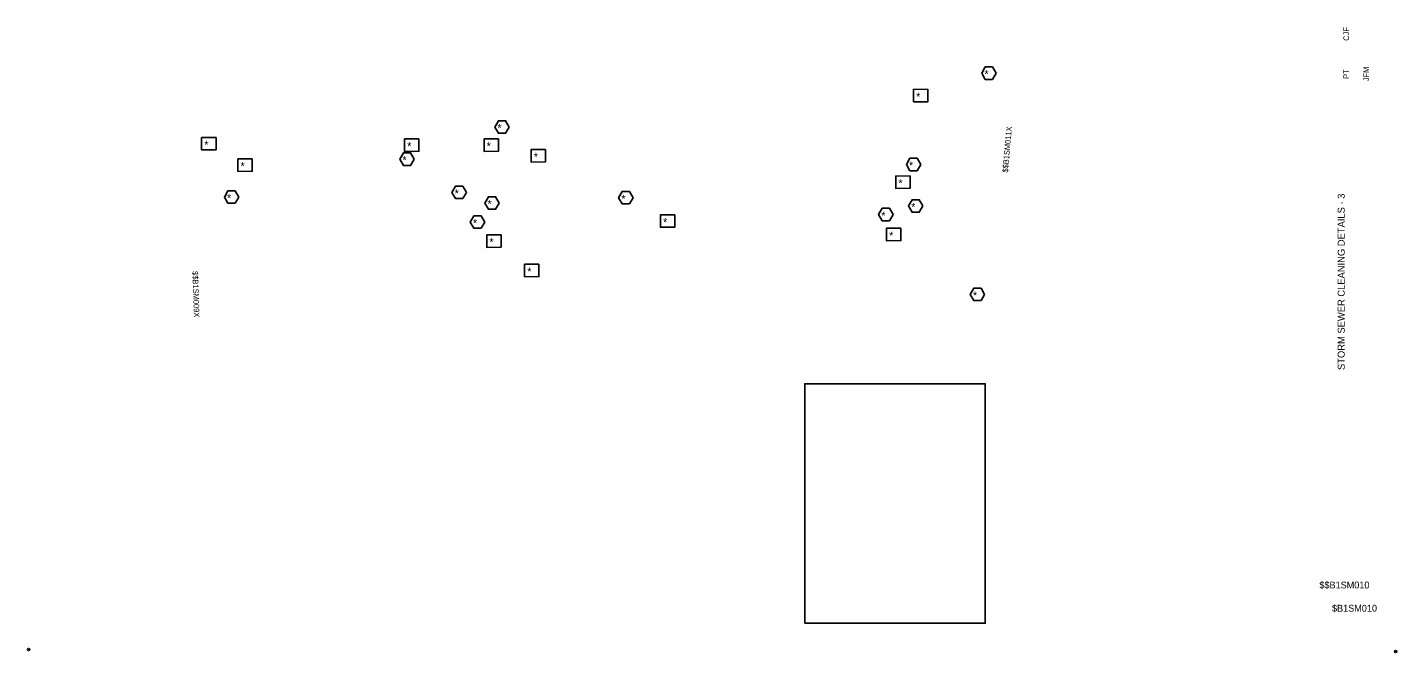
# Model space of a CAD drawing. Extents: x -0.1 to 34.1, y 0.1 to 15.7.
import ezdxf

# ---------------------------------------------------------------- set-up
doc = ezdxf.new("R2010")
doc.units = 0
for name, color, linetype in [('Default', 7, 'Continuous'), ('SC_Scratch1', 7, 'Continuous'), ('SH_Data', 7, 'Continuous')]:
    doc.layers.add(name, color=color, linetype=linetype)

msp = doc.modelspace()

# ---------------------------------------------------------------- linework, layer by layer
at = {"layer": 'Default'}
for p, q in [((-0.132, 0.139), (-0.08, 0.139)), ((-0.106, 0.139), (-0.057, 0.139)), ((34.043, 0.087), (34.095, 0.087)), ((34.069, 0.087), (34.118, 0.087))]:
    msp.add_line(p, q, dxfattribs=at)
msp.add_lwpolyline([(19.3, 0.793), (23.813, 0.793), (23.813, 6.783), (19.3, 6.783)], close=True, dxfattribs=at)
for centre in [(-0.106, 0.139), (34.069, 0.087)]:
    msp.add_circle(centre, 0.026, dxfattribs=at)
at = {"layer": 'SC_Scratch1'}
for points in [[(24.082, 14.545), (23.992, 14.701), (23.812, 14.701), (23.722, 14.545), (23.812, 14.389), (23.992, 14.389)], [(22.376, 14.143), (22.016, 14.139), (22.016, 13.828), (22.376, 13.832)], [(11.911, 13.198), (11.821, 13.354), (11.641, 13.354), (11.551, 13.198), (11.641, 13.042), (11.821, 13.042)], [(4.583, 12.94), (4.223, 12.936), (4.223, 12.625), (4.583, 12.629)], [(9.656, 12.905), (9.296, 12.901), (9.296, 12.589), (9.656, 12.593)], [(11.641, 12.905), (11.282, 12.901), (11.282, 12.589), (11.641, 12.593)], [(5.489, 12.405), (5.129, 12.402), (5.129, 12.09), (5.489, 12.094)], [(9.536, 12.395), (9.446, 12.551), (9.266, 12.551), (9.176, 12.395), (9.266, 12.24), (9.446, 12.24)], [(12.818, 12.639), (12.458, 12.635), (12.458, 12.323), (12.818, 12.327)], [(22.199, 12.263), (22.109, 12.418), (21.929, 12.418), (21.839, 12.263), (21.929, 12.107), (22.109, 12.107)], [(10.84, 11.565), (10.75, 11.72), (10.57, 11.72), (10.48, 11.565), (10.57, 11.409), (10.75, 11.409)], [(21.934, 11.978), (21.574, 11.974), (21.574, 11.662), (21.934, 11.666)], [(5.151, 11.449), (5.061, 11.605), (4.881, 11.605), (4.791, 11.449), (4.881, 11.293), (5.061, 11.293)], [(11.662, 11.299), (11.572, 11.454), (11.392, 11.454), (11.302, 11.299), (11.392, 11.143), (11.572, 11.143)], [(15.006, 11.432), (14.916, 11.588), (14.736, 11.588), (14.646, 11.432), (14.736, 11.276), (14.916, 11.276)], [(22.252, 11.226), (22.162, 11.382), (21.982, 11.382), (21.892, 11.226), (21.982, 11.07), (22.162, 11.07)], [(11.298, 10.822), (11.208, 10.978), (11.028, 10.978), (10.939, 10.822), (11.028, 10.666), (11.208, 10.666)], [(16.05, 11.006), (15.691, 11.002), (15.691, 10.691), (16.05, 10.695)], [(21.506, 11.01), (21.416, 11.166), (21.236, 11.166), (21.146, 11.01), (21.236, 10.854), (21.416, 10.854)], [(21.701, 10.671), (21.341, 10.667), (21.341, 10.355), (21.701, 10.359)], [(11.708, 10.506), (11.348, 10.502), (11.348, 10.19), (11.708, 10.194)], [(12.656, 9.772), (12.296, 9.768), (12.296, 9.457), (12.656, 9.46)], [(23.795, 9.013), (23.705, 9.169), (23.525, 9.169), (23.435, 9.013), (23.525, 8.858), (23.705, 8.858)]]:
    msp.add_lwpolyline(points, close=True, dxfattribs=at)

# ---------------------------------------------------------------- texts
at = {"layer": 'Default'}
for s, p in [('####', (-0.111, 0.129)), ('1', (-0.107, 0.145)), ('Drawing', (-0.073, 0.145)), ('Engr 1:1', (-0.073, 0.129)), ('####', (34.064, 0.077)), ('2', (34.068, 0.093)), ('Ref', (34.102, 0.093)), ('Engr 1:1', (34.102, 0.077))]:
    msp.add_text(s, height=0.00328, dxfattribs=at).set_placement(p)
at = {"layer": 'SC_Scratch1'}
for p in [(23.789, 14.42), (22.083, 13.859), (11.618, 13.074), (4.29, 12.656), (9.363, 12.62), (11.349, 12.62), (9.243, 12.271), (12.525, 12.355), (21.906, 12.138), (5.196, 12.121), (21.641, 11.694), (4.858, 11.324), (10.547, 11.44), (11.369, 11.174), (14.713, 11.307), (21.213, 10.885), (21.959, 11.102), (11.006, 10.698), (15.758, 10.722), (11.415, 10.222), (21.408, 10.386), (12.363, 9.488), (23.502, 8.889)]:
    msp.add_text('*', height=0.2, dxfattribs=at).set_placement(p)
for s, rotation, p in [('$$B1SM011X', 84.9655, (24.377, 12.055)), ('$$B1SM009X', 271.9111, (3.992, 9.594))]:
    msp.add_text(s, height=0.14, rotation=rotation, dxfattribs=at).set_placement(p)
at = {"layer": 'SH_Data'}
for s, height, p in [('CJF', 0.14, (32.903, 15.353)), ('PT', 0.14, (32.903, 14.401)), ('JFM', 0.14, (33.403, 14.344)), ('STORM SEWER CLEANING DETAILS - 3', 0.175, (32.796, 7.125))]:
    msp.add_text(s, height=height, rotation=90, dxfattribs=at).set_placement(p)
for s, p in [('$$B1SM010', (32.163, 1.665)), ('$B1SM010', (32.479, 1.085))]:
    msp.add_text(s, height=0.17, dxfattribs=at).set_placement(p)

doc.saveas('drawing.dxf')
